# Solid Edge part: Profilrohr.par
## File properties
Username: bmolnar
Dokumentum tartalom típus: 0
Author: bmolnar
Last saved by: bmolnar
Revision: 101
Sűrűség: 0,000 kg/m^3
Pontosság: 0,990
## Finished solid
Body 1: solid body, 175 faces, 519 edges, 346 vertices.
  Faces by surface: cylinder 107, plane 68
  Edges by curve: line 305, circle 214
Bounding box of the edges (mm): 60.200 x 60.200 x 1544.000, from (-30.1, -30.1, -1009.5) to (30.1, 30.1, 534.5).
Cylindrical faces by radius (mm): R0.1 x16, R0.2 x30, R0.5 x28, R1 x8, R3.75 x8, R5 x4, R6 x4, R25 x1, R27 x8
Planar faces by outward normal: +x 6, +y 6, +z 1, -x 4, -y 4, -z 1, oblique 46
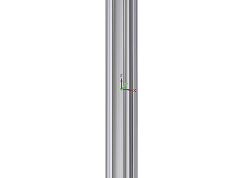
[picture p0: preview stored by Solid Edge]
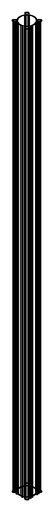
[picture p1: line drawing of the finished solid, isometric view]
